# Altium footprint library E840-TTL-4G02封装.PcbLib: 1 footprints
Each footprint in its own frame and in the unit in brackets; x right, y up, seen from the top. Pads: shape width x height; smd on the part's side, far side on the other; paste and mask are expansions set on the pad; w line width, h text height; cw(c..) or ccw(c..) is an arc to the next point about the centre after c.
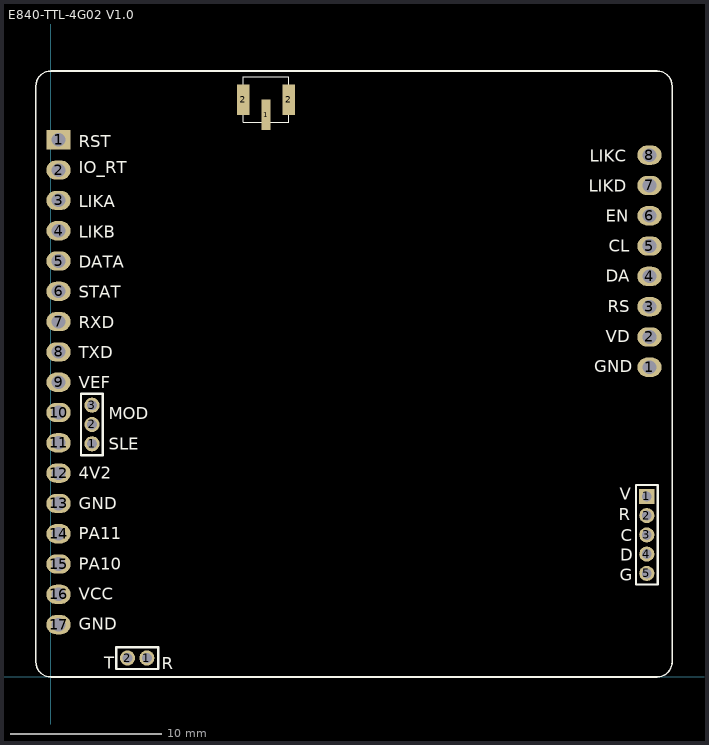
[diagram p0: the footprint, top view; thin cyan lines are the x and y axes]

## E840-TTL-4G02 V1.0 [mm]
pads (38):
  rect 1.6x1.27 hole 0.9: 1(0.5,35.455)
  round 1 hole 0.65 mask+0.05: 1(2.709,15.393) 1(6.327,1.253) 2(2.709,16.666) 2(5.054,1.253) 2(39.323,10.65) 3(2.709,17.937) 3(39.323,9.38) 4(39.323,8.11) 5(39.323,6.84)
  rect 0.6x2 smd: 1(14.193,37.107)
  rect 1x1 hole 0.65 mask+0.05: 1(39.323,11.92)
  oval 1.6x1.27 hole 0.9: 1(39.5,20.442) 2(0.5,33.455) 2(39.5,22.442) 3(0.5,31.455) 3(39.5,24.442) 4(0.5,29.455) 4(39.5,26.442) 5(0.5,27.455) 5(39.5,28.442) 6(0.5,25.455) 6(39.5,30.442) 7(0.5,23.455) 7(39.5,32.442) 8(0.5,21.455) 8(39.5,34.442) 9(0.5,19.455) 10(0.5,17.455) 11(0.5,15.455) 12(0.5,13.455) 13(0.5,11.455) 14(0.5,9.455) 15(0.5,7.455) 16(0.5,5.455) 17(0.5,3.455)
  rect 0.8x2 smd: 2(12.693,38.107) 2(15.693,38.107)
Mid-Layer 2:
  lines w0.254: 0.351,20.991 0.928,20.991
Top Overlay:
  lines w0.076: 12.693,36.607 12.693,39.607 15.693,39.607 15.693,36.607 12.693,36.607
  lines w0.1: -1,1 ccw(c0,1) 0,0 40,0 ccw(c40,1) 41,1 41,39 ccw(c40.002,38.998) 40,39.996 0,39.996 ccw(c-0.002,38.998) -1,39 -1,1
  lines w0.15: 1.987,14.635 1.987,18.695 3.423,18.695 3.423,14.635 1.987,14.635 ; 4.301,0.531 7.085,0.531 7.085,1.967 4.301,1.967 4.301,0.531 ; 38.61,6.107 40.045,6.107 40.045,12.678 38.61,12.678 38.61,6.107
  text "T" at 3.514,0.54 h0.8
  text "R" at 7.311,0.511 h0.8
  text "G" at 37.545,6.354 h0.8
  text "D" at 37.564,7.666 h0.8
  text "C" at 37.602,8.971 h0.8
  text "R" at 37.487,10.348 h0.8
  text "V" at 37.538,11.697 h0.8
  text "GND" at 35.87,20.108 h0.8
  text "VD" at 36.629,22.096 h0.8
  text "RS" at 36.743,24.083 h0.8
  text "DA" at 36.625,26.071 h0.8
  text "CL" at 36.808,28.058 h0.8
  text "EN" at 36.622,30.046 h0.8
  text "LIKD" at 35.498,32.033 h0.8
  text "LIKC" at 35.574,34.021 h0.8
  text "GND" at 1.838,3.112 h0.8
  text "VCC" at 1.838,5.103 h0.8
  text "PA10" at 1.838,7.094 h0.8
  text "PA11" at 1.838,9.086 h0.8
  text "GND" at 1.838,11.077 h0.8
  text "4V2" at 1.838,13.068 h0.8
  text "SLE" at 3.829,14.984 h0.8
  text "MOD" at 3.829,17.016 h0.8
  text "VEF" at 1.838,19.042 h0.8
  text "TXD" at 1.838,21.033 h0.8
  text "RXD" at 1.838,23.024 h0.8
  text "STAT" at 1.838,25.016 h0.8
  text "DATA" at 1.838,27.007 h0.8
  text "LIKB" at 1.838,28.998 h0.8
  text "LIKA" at 1.838,30.989 h0.8
  text "IO_RT" at 1.838,33.247 h0.8
  text "RST" at 1.838,34.972 h0.8
Bottom Overlay:
  lines w0.1: 27.355,17.327 22.895,17.327 22.895,0.127 38.195,0.127 38.195,15.767 38.195,15.937 27.365,15.937 ; 27.359,15.937 27.372,17.327
  lines w0.203: -0.719,34.439 1.719,34.439 ; 38.281,21.458 40.719,21.458 ; 40.694,35.712 38.281,35.712 38.281,19.198 40.719,19.198 40.719,35.712 ; -0.719,2.295 -0.719,36.7 1.719,36.7 1.719,2.295 -0.719,2.295
  text "P" at 3.746,17.637 h0.8
  text "V" at 3.694,15.008 h0.8
  text "M" at 3.746,16.284 h0.8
